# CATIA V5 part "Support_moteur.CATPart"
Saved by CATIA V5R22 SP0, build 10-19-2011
Part number: Part1
Bounding box of the stored display mesh (mm): x -20 to 60.11, y 0 to 82.4, z 0 to 36
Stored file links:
  C:\Users\eugen\OneDrive\Documents\cours\S9\PER\Support_moteur.CATPart
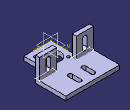
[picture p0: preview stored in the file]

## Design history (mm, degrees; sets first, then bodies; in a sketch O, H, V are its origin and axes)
Body1 (main body)
  Sketch1 on xy-plane, origin (0, 0, 0), H (1, 0, 0), V (0, 1, 0)
    line L1 (0, 0) -> (40.1098, 0)
    line L2 (40.1098, 0) -> (40.1098, 37.4)
    arc A1 centre (20.0549, 21.65) radius 12.65 from (15.1254, 33.3) to (15.1254, 10) ccw
    point P2 (20.0549, 21.65)
    arc A2 centre (9.9049, 72.4) radius 3.15 from (13.0549, 72.4) to (6.7549, 72.4) ccw
    point P3 (9.9049, 72.4)
    arc A3 centre (9.9049, 59.1) radius 3.15 from (6.7549, 59.1) to (13.0549, 59.1) ccw
    line L3 (13.0549, 59.1) -> (13.0549, 72.4)
    line L4 (6.7549, 59.1) -> (6.7549, 72.4)
    arc A4 centre (30.2049, 72.4) radius 3.15 from (33.3549, 72.4) to (27.0549, 72.4) ccw
    line L5 (27.0549, 59.1) -> (27.0549, 72.4)
    line L6 (33.3549, 59.1) -> (33.3549, 72.4)
    arc A5 centre (30.2049, 59.1) radius 3.15 from (27.0549, 59.1) to (33.3549, 59.1) ccw
    construction line L7 (-52.5175, 55.95) -> (-12.4077, 55.95)
    line L8 (15.1254, 10) -> (24.9844, 10)
    point P17 (15.1254, 10)
    point P18 (24.9844, 10)
    line L9 (15.1254, 33.3) -> (24.9844, 33.3)
    arc A6 centre (20.0549, 21.65) radius 12.65 from (24.9844, 10) to (24.9844, 33.3) ccw
    construction line L10 (24.9844, 33.3) -> (24.9844, 10)
    construction line L11 (15.1254, 33.3) -> (15.1254, 10)
    point P21 (15.1254, 10)
    circle A7 centre (7.6805, 34.0244) radius 2.15
    circle A8 centre (32.4292, 9.2756) radius 2.15
    construction line L12 (7.6805, 34.0244) -> (32.4292, 9.2756)
    construction line L13 (32.4292, 34.0244) -> (7.6805, 9.2756)
    point P24 (32.4292, 34.0244)
    point P25 (7.6805, 9.2756)
    point P26 (20.0549, 21.65)
    circle A9 centre (32.4292, 34.0244) radius 2.15
    point P27 (32.4292, 34.0244)
    circle A10 centre (7.6805, 9.2756) radius 2.15
    point P28 (7.6805, 9.2756)
    construction line L14 (32.4292, 9.2756) -> (7.6805, 9.2756)
    construction line L15 (0, 21.65) -> (40.1098, 21.65)
    point P29 (0, 21.65)
    point P30 (40.1098, 21.65)
    line L16 (-20, 82.4) -> (60.1098, 82.4)
    line L17 (60.1098, 82.4) -> (60.1098, 37.4)
    line L18 (60.1098, 37.4) -> (40.1098, 37.4)
    line L19 (-20, 37.4) -> (-20, 82.4)
    construction circle A11 centre (20.0549, 21.65) radius 21
    line L20 (0, 37.4) -> (0, 0)
    point P36 (0, 37.4)
    line L21 (0, 37.4) -> (-20, 37.4)
    distance L3 L4 = 6.3
    length L3 = 13.3
    length L6 = 13.3 {= Sketch1.length(L3)}
    distance L6 L5 = 6.3 {= Sketch1.distance(L3 L4)}
    radius A1 = 12.65
    distance L7 P2 = 34.3
    distance L6 L2 = 6.7549
    distance L9 L8 = 23.3
    radius A7 = 2.15
    length L12 = 35
    length L13 = 35 {= Sketch1.length(L12)}
    radius A8 = 2.15 {= Sketch1.radius(A7)}
    radius A9 = 2.15 {= Sketch1.radius(A7)}
    radius A10 = 2.15 {= Sketch1.radius(A7)}
    distance L8 L1 = 10
    distance L5 L3 = 14
    distance L2 L17 = 20
    radius A11 = 21
    distance L20 L4 = 6.7549 {= Sketch1.distance(L6 L2)}
    distance L19 L20 = 20 {= Sketch1.distance(L2 L17)}
    distance L16 P3 = 10
    distance L21 L16 = 45
    horizontal: L1 H, L7 H, L8 H, L9 H, L16 H, L18 H, L21 H
    vertical: L2 V, L17 V, L19 V, L20 V
    tangency: L4 A2, L3 A2, A3 L3, L4 A3, L5 A4, L6 A4, A5 L6, L5 A5, A3 L7, A5 L7
    parallelism: L7 L1, L10 L11, L14 L8
    coincidence: P18 A1, A1 A6, P21 P17, P26 L13, P26 L12, P27 L13, P24 P27, P28 L13, P28 P25, P26 P2, P30 L2, L15 P2, L18 P36, P29 L20, L18 L21
    perpendicularity: L13 L12, L15 L2
    midpoint: P26 L12, P26 L13, P2 L15
  Pad1: profile Sketch1, direction (0, 0, 1), length 6
  Sketch2 on end face of Pad1, origin (0, 0, 6), H (1, 0, 0), V (0, 1, 0)
    line L1 (34.69, 43.4) -> (60.1098, 43.4)
    line L2 (60.1098, 43.4) -> (60.1098, 37.4)
    line L3 (60.1098, 37.4) -> (34.69, 37.4)
    line L4 (34.69, 37.4) -> (34.69, 43.4)
    point P4 (34.69, 37.4)
    reference projected line E1 (40.1098, 37.4) -> (60.1098, 37.4) from edge [face of Pad1 from Sketch1.L18 | end face of Pad1]
    reference projected line E2 (60.1098, 37.4) -> (60.1098, 82.4) from edge [face of Pad1 from Sketch1.L17 | end face of Pad1]
    point P5 (5.4197, 37.4)
    line L5 (5.4197, 37.4) -> (-20, 37.4)
    line L6 (-20, 37.4) -> (-20, 43.4)
    line L7 (-20, 43.4) -> (5.4197, 43.4)
    line L8 (5.4197, 43.4) -> (5.4197, 37.4)
    point P6 (-20, 37.4)
    reference projected point E3 (-20, 37.4) from vertex [face of Pad1 from Sketch1.L21 | end face of Pad1 | face of Pad1 from Sketch1.L19]
    construction circle A1 centre (20.0549, 21.65) radius 21.5
    reference projected arc E4 centre (20.0549, 21.65) radius 12.65 from (15.1254, 33.3) to (15.1254, 10) ccw from edge [end face of Pad1 | face of Pad1 from Sketch1.A1]
    length L2 = 6
    length L6 = 6
    radius A1 = 21.5
    horizontal: L1 H, L3 H, L5 H, L7 H
    vertical: L2 V, L4 V, L6 V, L8 V
    coincidence: L3 E1, L2 E2, P6 E3, P5 A1, P4 A1
    concentricity: A1 E4
  Sketch3 on end face of Pad1, origin (0, 0, 6), H (1, 0, 0), V (0, 1, 0)
    line L1 (34.69, 43.4) -> (60.1098, 43.4)
    line L2 (60.1098, 43.4) -> (60.1098, 37.4)
    line L3 (60.1098, 37.4) -> (34.69, 37.4)
    line L4 (34.69, 37.4) -> (34.69, 43.4)
    point P4 (34.69, 37.4)
    reference projected line E1 (40.1098, 37.4) -> (60.1098, 37.4) from edge [face of Pad1 from Sketch1.L18 | end face of Pad1]
    reference projected line E2 (60.1098, 37.4) -> (60.1098, 82.4) from edge [face of Pad1 from Sketch1.L17 | end face of Pad1]
    point P5 (5.4197, 37.4)
    line L5 (5.4197, 37.4) -> (-20, 37.4)
    line L6 (-20, 37.4) -> (-20, 43.4)
    line L7 (-20, 43.4) -> (5.4197, 43.4)
    line L8 (5.4197, 43.4) -> (5.4197, 37.4)
    point P6 (-20, 37.4)
    reference projected point E3 (-20, 37.4) from vertex [face of Pad1 from Sketch1.L21 | end face of Pad1 | face of Pad1 from Sketch1.L19]
    construction circle A1 centre (20.0549, 21.65) radius 21.5
    reference projected arc E4 centre (20.0549, 21.65) radius 12.65 from (15.1254, 33.3) to (15.1254, 10) ccw from edge [end face of Pad1 | face of Pad1 from Sketch1.A1]
    length L2 = 6
    length L6 = 6
    radius A1 = 21.5
    horizontal: L1 H, L3 H, L5 H, L7 H
    vertical: L2 V, L4 V, L6 V, L8 V
    coincidence: L3 E1, L2 E2, P6 E3, P5 A1, P4 A1
    concentricity: A1 E4
  Pad2: profile Sketch2, direction (0, 0, 1), length 30
  Sketch4 on face of Pad2, origin (0, 37.4, 0), H (1, 0, 0), V (0, 0, 1)
    arc A1 centre (-7.2901, 27.65) radius 3.1499 from (-4.1403, 27.65) to (-10.44, 27.65) ccw
    line L1 (-10.44, 14.35) -> (-10.44, 27.65)
    line L2 (-4.1403, 14.35) -> (-4.1403, 27.65)
    arc A2 centre (-7.2901, 14.35) radius 3.1499 from (-10.44, 14.35) to (-4.1403, 14.35) ccw
    arc A3 centre (47.3999, 27.65) radius 3.1499 from (50.5498, 27.65) to (44.25, 27.65) ccw
    line L3 (44.25, 14.35) -> (44.25, 27.65)
    line L4 (50.5498, 14.35) -> (50.5498, 27.65)
    arc A4 centre (47.3999, 14.35) radius 3.1499 from (44.25, 14.35) to (50.5498, 14.35) ccw
    reference projected line E1 (60.1098, 0) -> (60.1098, 6) from edge [face of Pad2 | face of Pad2]
    reference projected line E2 (60.1098, 0) -> (60.1098, 6) from edge [face of Pad2 | face of Pad2]
    reference projected line E3 (34.69, 6) -> (34.69, 36) from edge [face of Pad2 from Sketch2.L3 | face of Pad2 from Sketch2.L4]
    reference projected line E4 (5.4197, 6) -> (5.4197, 36) from edge [face of Pad2 from Sketch2.L8 | face of Pad2 from Sketch2.L5]
    reference projected line E5 (-20, 0) -> (-20, 6) from edge [face of Pad2 | face of Pad2]
    point P13 (50.5498, 21)
    construction line L5 (50.5498, 6) -> (50.5498, 36)
    point P14 (50.5498, 6)
    point P15 (50.5498, 36)
    reference projected line E6 (34.69, 36) -> (60.1098, 36) from edge [face of Pad2 | end face of Pad2]
    reference projected line E7 (34.69, 6) -> (60.1098, 6) from Sketch2.L3
    construction line L6 (-10.44, 36) -> (-10.44, 6)
    point P16 (-10.44, 36)
    point P17 (-10.44, 6)
    reference projected line E8 (5.4197, 6) -> (-20, 6) from Sketch2.L7
    reference projected line E9 (-20, 36) -> (5.4197, 36) from edge [face of Pad2 | end face of Pad2]
    point P18 (-10.44, 21)
    length L1 = 13.3
    distance E2 L4 = 9.56
    distance L3 E3 = 9.56
    distance L3 L4 = 6.2997 (reference)
    distance L2 E4 = 9.56
    distance L1 E5 = 9.56
    distance L1 L2 = 6.2997 (reference)
    length L4 = 13.3
    tangency: L1 A1, L2 A1, A2 L2, L1 A2, L3 A3, L4 A3, A4 L4, L3 A4
    parallelism: E1 L4, L3 L2
    midpoint: P13 L4, P13 L5, P18 L1, P18 L6
    coincidence: P15 E6, P14 E7, L5 L4, P17 E8, P16 E9, P18 L1
    vertical: L6 V
  Pocket1: profile Sketch4, direction (0, 1, 0), through (limit type 6)
  Sketch5 on face of Pad2, origin (0, 37.4, -37.4), H (1, 0, 0), V (0, 0, 1)
    line L1 (0, 0) -> (40.1098, 0)
    line L2 (40.1098, 0) -> (40.1098, 37.4)
    arc A1 centre (20.0549, 21.65) radius 12.65 from (15.1254, 33.3) to (15.1254, 10) ccw
    point P2 (20.0549, 21.65)
    arc A2 centre (9.9049, 72.4) radius 3.15 from (13.0549, 72.4) to (6.7549, 72.4) ccw
    point P3 (9.9049, 72.4)
    arc A3 centre (9.9049, 59.1) radius 3.15 from (6.7549, 59.1) to (13.0549, 59.1) ccw
    line L3 (13.0549, 59.1) -> (13.0549, 72.4)
    line L4 (6.7549, 59.1) -> (6.7549, 72.4)
    arc A4 centre (30.2049, 72.4) radius 3.15 from (33.3549, 72.4) to (27.0549, 72.4) ccw
    line L5 (27.0549, 59.1) -> (27.0549, 72.4)
    line L6 (33.3549, 59.1) -> (33.3549, 72.4)
    arc A5 centre (30.2049, 59.1) radius 3.15 from (27.0549, 59.1) to (33.3549, 59.1) ccw
    construction line L7 (-52.5175, 55.95) -> (-12.4077, 55.95)
    line L8 (15.1254, 10) -> (24.9844, 10)
    point P17 (15.1254, 10)
    point P18 (24.9844, 10)
    line L9 (15.1254, 33.3) -> (24.9844, 33.3)
    arc A6 centre (20.0549, 21.65) radius 12.65 from (24.9844, 10) to (24.9844, 33.3) ccw
    construction line L10 (24.9844, 33.3) -> (24.9844, 10)
    construction line L11 (15.1254, 33.3) -> (15.1254, 10)
    point P21 (15.1254, 10)
    circle A7 centre (7.6805, 34.0244) radius 2.15
    circle A8 centre (32.4292, 9.2756) radius 2.15
    construction line L12 (7.6805, 34.0244) -> (32.4292, 9.2756)
    construction line L13 (32.4292, 34.0244) -> (7.6805, 9.2756)
    point P24 (32.4292, 34.0244)
    point P25 (7.6805, 9.2756)
    point P26 (20.0549, 21.65)
    circle A9 centre (32.4292, 34.0244) radius 2.15
    point P27 (32.4292, 34.0244)
    circle A10 centre (7.6805, 9.2756) radius 2.15
    point P28 (7.6805, 9.2756)
    construction line L14 (32.4292, 9.2756) -> (7.6805, 9.2756)
    construction line L15 (0, 21.65) -> (40.1098, 21.65)
    point P29 (0, 21.65)
    point P30 (40.1098, 21.65)
    line L16 (-20, 82.4) -> (60.1098, 82.4)
    line L17 (60.1098, 82.4) -> (60.1098, 37.4)
    line L18 (60.1098, 37.4) -> (40.1098, 37.4)
    line L19 (-20, 37.4) -> (-20, 82.4)
    construction circle A11 centre (20.0549, 21.65) radius 21
    line L20 (0, 37.4) -> (0, 0)
    point P36 (0, 37.4)
    line L21 (0, 37.4) -> (-20, 37.4)
    distance L3 L4 = 6.3
    length L3 = 13.3
    length L6 = 13.3 {= Sketch5.length(L3)}
    distance L6 L5 = 6.3 {= Sketch5.distance(L3 L4)}
    radius A1 = 12.65
    distance L7 P2 = 34.3
    distance L6 L2 = 6.7549
    distance L9 L8 = 23.3
    radius A7 = 2.15
    length L12 = 35
    length L13 = 35 {= Sketch5.length(L12)}
    radius A8 = 2.15 {= Sketch5.radius(A7)}
    radius A9 = 2.15 {= Sketch5.radius(A7)}
    radius A10 = 2.15 {= Sketch5.radius(A7)}
    distance L8 L1 = 10
    distance L5 L3 = 14
    distance L2 L17 = 20
    radius A11 = 21
    distance L20 L4 = 6.7549 {= Sketch5.distance(L6 L2)}
    distance L19 L20 = 20 {= Sketch5.distance(L2 L17)}
    distance L16 P3 = 10
    distance L21 L16 = 45
    horizontal: L1 H, L7 H, L8 H, L9 H, L16 H, L18 H, L21 H
    vertical: L2 V, L17 V, L19 V, L20 V
    tangency: L4 A2, L3 A2, A3 L3, L4 A3, L5 A4, L6 A4, A5 L6, L5 A5, A3 L7, A5 L7
    parallelism: L7 L1, L10 L11, L14 L8
    coincidence: P18 A1, A1 A6, P21 P17, P26 L13, P26 L12, P27 L13, P24 P27, P28 L13, P28 P25, P26 P2, P30 L2, L15 P2, L18 P36, P29 L20, L18 L21
    perpendicularity: L13 L12, L15 L2
    midpoint: P26 L12, P26 L13, P2 L15
  Pad3: profile Sketch5, direction (0, -1, 0), length 6
Current feature: Pocket1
